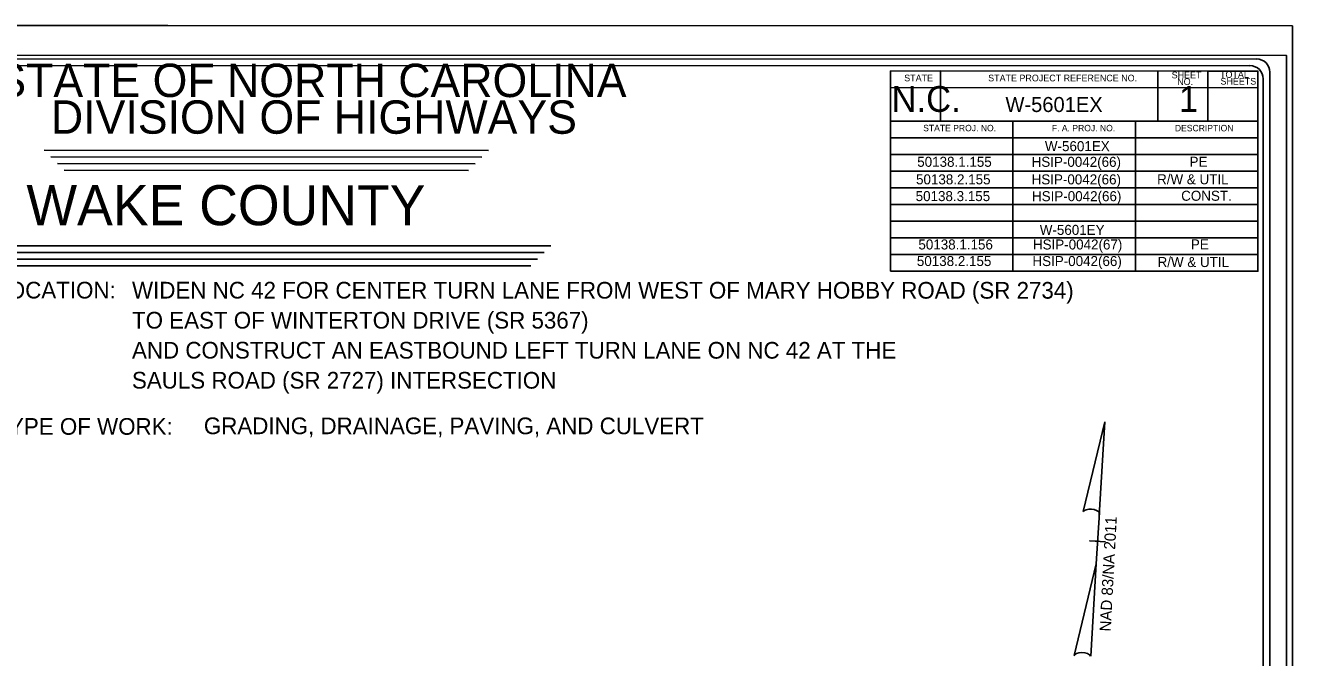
# Model space of a CAD drawing. Extents: x 2105791 to 2114488, y 667759 to 673441.
# Drawn here: x 2109589 to 2114488, y 670994 to 673441 of the extents above; entities that cross this region are included whole.
import ezdxf

# ---------------------------------------------------------------- set-up
doc = ezdxf.new("R2010")
doc.units = 0
for name, color, linetype in [('Old_Level_1', 7, 'Continuous'), ('Prop North Arrow NAD83 for Plan Sheets CELL', 7, 'Continuous'), ('Sheet Cutting Line CELL', 7, 'Continuous'), ('Sheet Data Field CELL', 7, 'Continuous'), ('Sheet Plot Border Inside CELL', 7, 'Continuous'), ('Sheet Plot Border Outside CELL', 7, 'Continuous'), ('Sheet Title CELL', 7, 'Continuous'), ('Sheet Title Data Points CELL', 7, 'Continuous')]:
    doc.layers.add(name, color=color, linetype=linetype)

msp = doc.modelspace()

# ---------------------------------------------------------------- linework, layer by layer
at = {"layer": 'Old_Level_1'}
for p, q in [((2113678, 671559.1), (2113761.5, 671906.6)), ((2113761.9, 671906.6), (2113739.8, 671544.3)), ((2113761.9, 671906.6), (2113761.5, 671906.6)), ((2113761.9, 671906.6), (2113761.5, 671906.6)), ((2113728.4, 671356.3), (2113740.5, 671554.9)), ((2113739.8, 671544.3), (2113740.5, 671554.5)), ((2113703.4, 671446.1), (2113703.1, 671446.1)), ((2113730.3, 671444.4), (2113703.4, 671446.1)), ((2113703.8, 671446), (2113764.5, 671442.4)), ((2113728.4, 671356.3), (2113643.3, 671002)), ((2113707.1, 670999.6), (2113728.4, 671356.3))]:
    msp.add_line(p, q, dxfattribs=at)
for centre, start_param, end_param in [((2113709.1, 671553.4), 0.216388, 2.908219), ((2113675.4, 670998.8), 0.201328, 3.141593)]:
    msp.add_ellipse(centre, major_axis=(32, -2.2), ratio=0.461098, start_param=start_param, end_param=end_param, dxfattribs=at)
at = {"layer": 'Sheet Cutting Line CELL'}
msp.add_line((2105792, 673440.8), (2114487.7, 673439.3), dxfattribs=at)
at = {"layer": 'Sheet Plot Border Inside CELL'}
msp.add_lwpolyline([(2105858.2, 667876.6), (2114463.6, 667875.1), (2114464.5, 673323.4), (2105859.1, 673324.8)], close=True, dxfattribs=at)
at = {"layer": 'Sheet Plot Border Outside CELL'}
msp.add_lwpolyline([(2114487.7, 673439.3), (2105792, 673440.8), (2105791, 667760.7), (2114486.8, 667759.2)], close=True, dxfattribs=at)
at = {"layer": 'Sheet Title CELL'}
for p, q in [((2109661.6, 672957.1), (2111379.8, 672956.8)), ((2109687.4, 672931.3), (2111354, 672930.9)), ((2109713.2, 672905.4), (2111328.2, 672905.2)), ((2109739.1, 672879.6), (2111302.4, 672879.4)), ((2109420.7, 672587.4), (2111620.4, 672587)), ((2109446.5, 672561.6), (2111594.6, 672561.2)), ((2109472.3, 672535.7), (2111568.8, 672535.4)), ((2109498.1, 672510), (2111542.9, 672509.6))]:
    msp.add_line(p, q, dxfattribs=at)
for points in [[(2114348.4, 673310.2), (2106705.9, 673311.6)], [(2114322.5, 673284.4), (2106990, 673285.7)], [(2112933.3, 672489.5), (2114353.3, 672489.3), (2114353.3, 672553.7), (2112933.3, 672554.1), (2112933.3, 672618.5), (2114353.3, 672618.3), (2114353.3, 672682.8), (2112933.4, 672683.1), (2112933.3, 672747.7), (2114353.4, 672747.5), (2114353.4, 672812), (2112933.3, 672812.2), (2112933.3, 672876.7), (2114353.4, 672876.5), (2114353.4, 672941), (2112933.4, 672941.3), (2112933.4, 673005.8), (2114353.4, 673005.6), (2114353.4, 673070.2), (2112933.4, 673070.4), (2112933.4, 673199.5), (2114353.4, 673199.3), (2114353.4, 673263.8), (2112933.4, 673264), (2112933.3, 672489.5), (2113406.5, 672489.4), (2113406.6, 673070.3), (2113127, 673070.3), (2113127.1, 673264), (2113966.2, 673263.8), (2113966.1, 673070.3), (2113879.9, 673070.3), (2113879.8, 672489.3), (2114353.3, 672489.3), (2114353.4, 673263.8), (2114159.8, 673263.9), (2114159.8, 673070.2)], [(2114373.4, 668921), (2114374.1, 673232.8)], [(2114399, 667940), (2114399.9, 673258.6)]]:
    msp.add_lwpolyline(points, dxfattribs=at)
for centre in [(2114322.5, 673233.1), (2114348.3, 673258.9)]:
    msp.add_arc(centre, 51.6, 359.9903, 89.9903, dxfattribs=at)
at = {"layer": 'Sheet Title Data Points CELL'}
for p, q in [((2110528.6, 672664.2), (2110528.6, 672664.2)), ((2111148.4, 672383.4), (2111148.4, 672383.4))]:
    msp.add_line(p, q, dxfattribs=at)

# ---------------------------------------------------------------- texts
at = {"layer": 'Prop North Arrow NAD83 for Plan Sheets CELL'}
msp.add_text('NAD 83/NA 2011', height=43.531, rotation=86.95, dxfattribs=at).set_placement((2113784.5, 671094.1))
at = {"layer": 'Sheet Data Field CELL'}
for s, height, p in [('W-5601EX            ', 58.092, (2113377.7, 673105.3)), ('W-5601EX', 38.73, (2113530.1, 672953.8)), ('50138.1.155', 38.728, (2113036.6, 672893.2)), ('HSIP-0042(66)', 38.728, (2113478.8, 672893.1)), ('PE', 38.73, (2114089.2, 672893.5)), ('50138.2.155', 38.728, (2113032, 672825.3)), ('HSIP-0042(66)', 38.728, (2113478.8, 672825.2)), ('R/W & UTIL', 38.73, (2113963.8, 672825.6)), (' WAKE COUNTY  ', 154.912, (2109535.9, 672667.4)), ('50138.3.155', 38.728, (2113030.5, 672760.5)), ('HSIP-0042(66)', 38.728, (2113480.3, 672760.2)), ('CONST.     ', 38.728, (2114056.8, 672761.8)), ('W-5601EY', 38.73, (2113510.3, 672629.7)), ('50138.1.156', 38.728, (2113041.1, 672573.3)), ('HSIP-0042(67)', 38.728, (2113483.9, 672573.3)), ('PE', 38.73, (2114094.3, 672573.7)), ('50138.2.155', 38.728, (2113035.2, 672509.3)), ('HSIP-0042(66)', 38.728, (2113482, 672509.2)), ('R/W & UTIL', 38.73, (2113965.6, 672505.4)), ('WIDEN NC 42 FOR CENTER TURN LANE FROM WEST OF MARY HOBBY ROAD (SR 2734)', 64.547, (2110001.4, 672383.6)), ('TO EAST OF WINTERTON DRIVE (SR 5367)         ', 64.547, (2110001.4, 672267.4)), ('AND CONSTRUCT AN EASTBOUND LEFT TURN LANE ON NC 42 AT THE    ', 64.547, (2110001.3, 672151.3)), ('SAULS ROAD (SR 2727) INTERSECTION                            ', 64.547, (2110001.2, 672035.1)), ('GRADING, DRAINAGE, PAVING, AND CULVERT          ', 64.547, (2110279.1, 671858.6))]:
    msp.add_text(s, height=height, rotation=359.9903, dxfattribs=at).set_placement(p)
at = {"layer": 'Sheet Title CELL'}
for s, height, p in [('STATE OF NORTH CAROLINA', 129.093, (2109476.8, 673163.4)), ('STATE', 25.82, (2112986.3, 673224)), ('STATE PROJECT REFERENCE NO.', 25.818, (2113310.9, 673223.9)), ('SHEET', 25.82, (2114020.1, 673235.4)), ('NO.', 25.82, (2114041.5, 673209.9)), ('TOTAL', 25.82, (2114207, 673237.3)), ('SHEETS', 25.82, (2114208.8, 673211.4)), ('N.C.', 99.92, (2112937.3, 673105.8)), ('1', 99.9, (2114048, 673105.6)), ('DIVISION OF HIGHWAYS', 129.093, (2109688, 673021.4)), ('STATE PROJ. NO.', 24.786, (2113059.6, 673030.9)), ('F. A. PROJ. NO.', 24.786, (2113556.9, 673030.8)), ('DESCRIPTION', 24.786, (2114032.5, 673030.7)), ('LOCATION: ', 64.55, (2109473.3, 672383.7)), ('TYPE OF WORK:', 64.547, (2109473.2, 671856.3))]:
    msp.add_text(s, height=height, rotation=359.9903, dxfattribs=at).set_placement(p)

doc.saveas('drawing.dxf')
